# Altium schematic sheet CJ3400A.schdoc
size 127 x 101 mm
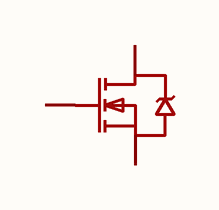
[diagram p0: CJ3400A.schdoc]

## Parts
Q?  cj3400a  [SOT-23-3_L3.0-W1.7-P0.95-LS2.9-BR]  (value not drawn)

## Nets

Not connected (* = marked no-connect by the designer): Q? 1(G) 2(S) 3(D)

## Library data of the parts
Q? = cj3400a: 数量:1个N沟道;漏源电压(Vdss):30V;连续漏极电流(Id):5.8A;导通电阻(RDS(on)):45mΩ@2.5V;耗散功率(Pd):400mW;阈值电压(Vgs(th)):700mV;; Manufacturer: CJ(江苏长电/长晶); AddInBom: yes; ModelId: 89cb27a44ab2466697082bb9fd73a7d0; ModelName: SOT-23-3L_L2.9-W1.6-H1.1-LS2.8-P0.95; ModelTransform: 114.173,110.236,0,90,0,0,0,0,0; Number: 1个N沟道; Drain to Source Voltage: 30V; Current - Continuous Drain(Id): 5.8A; Pd - Power Dissipation: 400mW; Gate Threshold Voltage (Vgs(th)): 700mV; Input Capacitance(Ciss): 1.155nF; Reverse Transfer Capacitance (Crss@Vds): 84pF; Type: N沟道; Output Capacitance(Coss): 108pF; Vgs: ±12V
